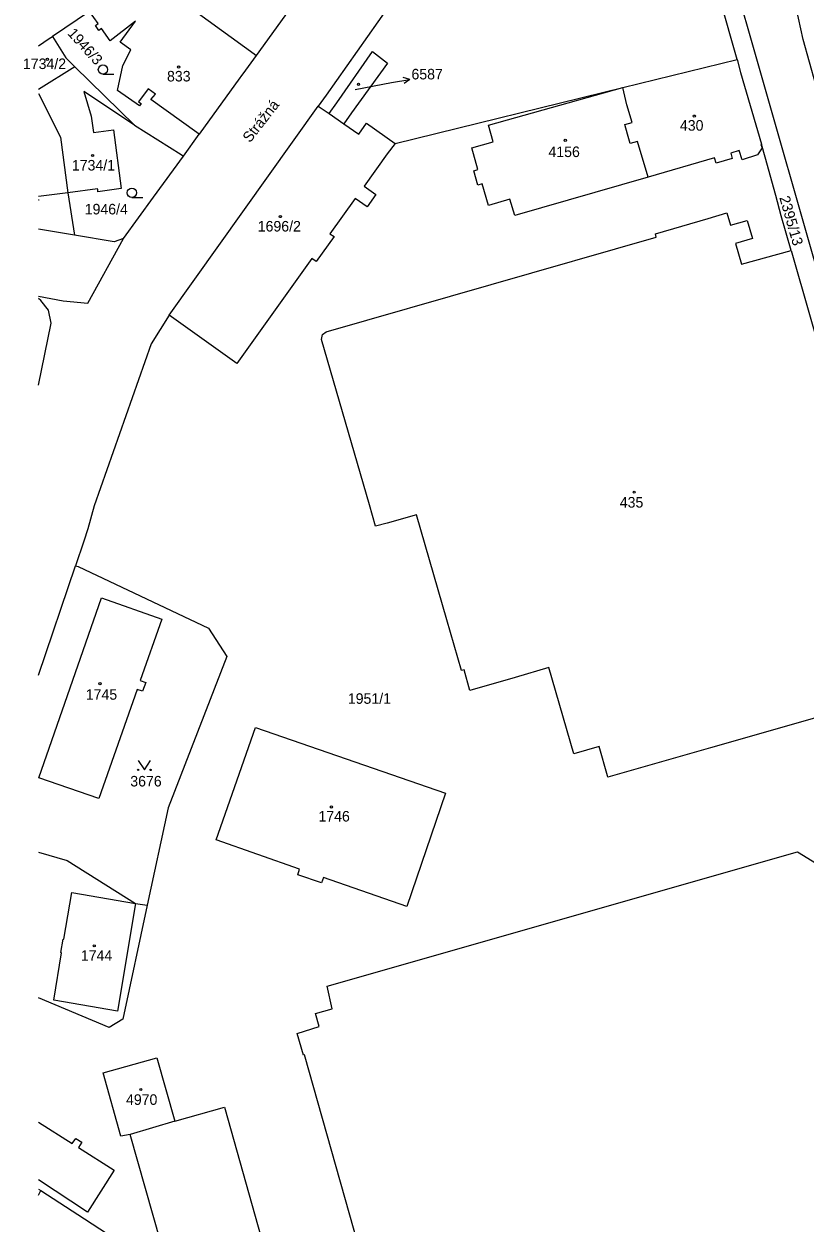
# Model space of a CAD drawing. Extents: x -667048 to -665920, y -1108425 to -1107247.
# Drawn here: x -667045.8 to -666919.9, y -1107600.6 to -1107407.4 of the extents above; entities that cross this region are included whole.
import ezdxf

# ---------------------------------------------------------------- set-up
doc = ezdxf.new("R2010")
doc.units = 0
for name, color, linetype in [('Default', 7, 'Continuous'), ('Hranice parcel', 7, 'Continuous'), ('Parcelní čísla', 7, 'Continuous'), ('Pop_ PČ_ popisy', 7, 'Continuous'), ('Značky budov', 7, 'Continuous'), ('Značky kultur', 7, 'Continuous')]:
    doc.layers.add(name, color=color, linetype=linetype)

# ---------------------------------------------------------------- blocks, each defined once
blk = doc.blocks.new('3.041')
at = {"layer": 'Default'}
blk.add_line((8, 0), (1758, 0), dxfattribs=at)
blk.add_circle((8, 750), 750, dxfattribs=at)
blk = doc.blocks.new('4.021')
at = {"layer": 'Default'}
blk.add_circle((-7, 1), 175, dxfattribs=at)
blk = doc.blocks.new('3.141')
at = {"layer": 'Default'}
blk.add_lwpolyline([(-1000, 1500), (0, 0), (1000, 1500)], dxfattribs=at)
for centre in [(-1000, 0), (1000, 0)]:
    blk.add_circle(centre, 100, dxfattribs=at)
blk = doc.blocks.new('10291')
at = {"layer": 'Default'}
for p, q in [((0, 3001), (-500, 2001)), ((0, 1), (0, 3001)), ((0, 3001), (500, 2001))]:
    blk.add_line(p, q, dxfattribs=at)

msp = doc.modelspace()

# ---------------------------------------------------------------- linework, layer by layer
at = {"layer": 'Hranice parcel'}
for points in [[(-666939.1, -1107384.26), (-666969.17, -1107379.15), (-666975.49, -1107388.12), (-666997.14, -1107418.9)], [(-666930.91, -1107413.15), (-666939.1, -1107384.26)], [(-666876.77, -1107557.56), (-666884.34, -1107546.73), (-666886.63, -1107542.65), (-666889.78, -1107536.12), (-666894, -1107526.85), (-666896.26, -1107521.29), (-666898.79, -1107514.08), (-666932.95, -1107394.82)], [(-667026.36, -1107399.54), (-667024.4, -1107400.87), (-667023.75, -1107401.31), (-667017.68, -1107405.72), (-667008.73, -1107412.23), (-667008.37, -1107412.49)], [(-666999.3, -1107399.88), (-667005.88, -1107408.97), (-667008.37, -1107412.49)], [(-666913.11, -1107435.5), (-666920.25, -1107409.89), (-666922.49, -1107399.52), (-666922.6, -1107398.73)], [(-667035.26, -1107405.41), (-667041.21, -1107409.4)], [(-667030.29, -1107410.32), (-667027.84, -1107406.98), (-667031.91, -1107410.1), (-667033.31, -1107408.14), (-667033.74, -1107408.45), (-667034.31, -1107407.66), (-667033.87, -1107407.35), (-667035.26, -1107405.41)], [(-667043.46, -1107410.91), (-667041.77, -1107409.77), (-667041.21, -1107409.4)], [(-667041.21, -1107409.4), (-667039.07, -1107412.88), (-667037.6, -1107414.3)], [(-667029.88, -1107414.11), (-667028.58, -1107411.57), (-667030.29, -1107410.32)], [(-667008.37, -1107412.49), (-667010.13, -1107414.86), (-667010.89, -1107415.89), (-667011.05, -1107416.1), (-667017.56, -1107425.16)], [(-666995.42, -1107420.09), (-666989.67, -1107411.85), (-666987.21, -1107413.74), (-666993.03, -1107421.75)], [(-666949.31, -1107417.64), (-666930.91, -1107413.15)], [(-666930.91, -1107413.15), (-666930.32, -1107415.21)], [(-667037.6, -1107414.3), (-667043.46, -1107417.98)], [(-667037.6, -1107414.3), (-667027.99, -1107423.72)], [(-667017.56, -1107425.16), (-667017.93, -1107424.9), (-667025.38, -1107419.59), (-667024.61, -1107418.72), (-667025.81, -1107417.85), (-667027.33, -1107419.95), (-667026.94, -1107420.23), (-667027.2, -1107420.6), (-667030.75, -1107418.12), (-667029.88, -1107414.11)], [(-666930.32, -1107415.21), (-666926.97, -1107426.78)], [(-667043.46, -1107418.61), (-667039.93, -1107425.62), (-667038.73, -1107434.59)], [(-667027.99, -1107423.72), (-667036.18, -1107418.29), (-667034.98, -1107422.28), (-667034.63, -1107424.91), (-667031.39, -1107424.48), (-667030.13, -1107433.94), (-667033.89, -1107434.45), (-667033.93, -1107434.14), (-667033.95, -1107433.95), (-667038.73, -1107434.59)], [(-666997.14, -1107418.9), (-666998.38, -1107420.63)], [(-666985.98, -1107426.64), (-666949.31, -1107417.64)], [(-666945.24, -1107432.09), (-666966.73, -1107438.28), (-666967.5, -1107435.63), (-666970.97, -1107436.64), (-666971.98, -1107433.18), (-666972.65, -1107433.37), (-666973.32, -1107431.07), (-666972.65, -1107430.88), (-666973.66, -1107427.39), (-666970.18, -1107426.38), (-666970.96, -1107423.72), (-666949.31, -1107417.64)], [(-666945.24, -1107432.09), (-666946.92, -1107426.33), (-666948.11, -1107426.67), (-666948.56, -1107425.14), (-666949, -1107423.6), (-666947.81, -1107423.26), (-666948.64, -1107420.43), (-666949.31, -1107417.64)], [(-667022.4, -1107454.32), (-666998.38, -1107420.63)], [(-666998.38, -1107420.63), (-666996.64, -1107421.83)], [(-666996.64, -1107421.83), (-666995.42, -1107420.09)], [(-666996.64, -1107421.83), (-666994.28, -1107423.47)], [(-666993.03, -1107421.75), (-666994.28, -1107423.47)], [(-667027.99, -1107423.72), (-667020.5, -1107428.45)], [(-667020.13, -1107428.71), (-667017.56, -1107425.16)], [(-666994.28, -1107423.47), (-666991.86, -1107425.15), (-666990.64, -1107423.41), (-666985.98, -1107426.64)], [(-666985.98, -1107426.64), (-666987.28, -1107428.33), (-666991.01, -1107433.53), (-666989.09, -1107434.86), (-666990.53, -1107436.87), (-666992.45, -1107435.54), (-666996.51, -1107441.2), (-666995.83, -1107441.67), (-666998.72, -1107445.69), (-666999.4, -1107445.22), (-667011.53, -1107462.12), (-667022.4, -1107454.32)], [(-666926.97, -1107426.78), (-666927.05, -1107426.8), (-666926.88, -1107427.38), (-666927.58, -1107428.51), (-666930.08, -1107429.3), (-666930.55, -1107427.82), (-666931.92, -1107428.22), (-666931.67, -1107429.08), (-666934.26, -1107429.84), (-666934.51, -1107428.97), (-666945.24, -1107432.09)], [(-666923.78, -1107438.31), (-666924.65, -1107435.04), (-666926.39, -1107428.87), (-666926.97, -1107426.78)], [(-667029.75, -1107441.98), (-667024.93, -1107435.33), (-667020.13, -1107428.71)], [(-667020.5, -1107428.45), (-667020.13, -1107428.71)], [(-667038.73, -1107434.59), (-667043.46, -1107435.23)], [(-667038.73, -1107434.59), (-667037.69, -1107441.43)], [(-667043.46, -1107435.67), (-667043.44, -1107435.78), (-667043.46, -1107435.78)], [(-666909.41, -1107516.68), (-666935.2, -1107524.05), (-666951.74, -1107528.77), (-666951.8, -1107528.57), (-666953.12, -1107523.85), (-666957.23, -1107525.01), (-666961.21, -1107511.12), (-666966.67, -1107512.7), (-666973.95, -1107514.81), (-666974.85, -1107511.45), (-666975.33, -1107511.59), (-666977.68, -1107503.41), (-666982.55, -1107486.49), (-666987.31, -1107487.83), (-666989.17, -1107488.35), (-666990.14, -1107484.88), (-666997.85, -1107458.23), (-666997.69, -1107457.45), (-666997.12, -1107457.02), (-666943.94, -1107441.76), (-666944.06, -1107441.22), (-666935.56, -1107438.73), (-666932.54, -1107437.85), (-666931.97, -1107439.83), (-666929.29, -1107439.06), (-666928.42, -1107441.96), (-666931.15, -1107442.76), (-666930.19, -1107446.1)], [(-666922.18, -1107443.88), (-666923.78, -1107438.31)], [(-667037.69, -1107441.43), (-667043.46, -1107440.45)], [(-667043.46, -1107451.24), (-667039.48, -1107451.99), (-667035.5, -1107452.41), (-667029.75, -1107441.98)], [(-667031.28, -1107442.52), (-667037.69, -1107441.43)], [(-667029.75, -1107441.98), (-667031.28, -1107442.52)], [(-666930.19, -1107446.1), (-666922.18, -1107443.88)], [(-666922.18, -1107443.88), (-666903.37, -1107509.56), (-666902.18, -1107513.45)], [(-667043.46, -1107465.63), (-667041.43, -1107455.64), (-667041.87, -1107453.53), (-667043.07, -1107451.95), (-667043.46, -1107451.64)], [(-667022.4, -1107454.32), (-667025.32, -1107458.97)], [(-667025.32, -1107458.97), (-667034.52, -1107485.06), (-667035.51, -1107488.76), (-667036.18, -1107490.74), (-667037.52, -1107494.7)], [(-667043.46, -1107512.33), (-667037.52, -1107494.7)], [(-667037.52, -1107494.7), (-667037.09, -1107494.85)], [(-667037.09, -1107494.85), (-667016.08, -1107504.77), (-667013.14, -1107509.35), (-667022.57, -1107533.69), (-667025.95, -1107549.42)], [(-667033.32, -1107499.86), (-667023.61, -1107503.31), (-667027.08, -1107513.2), (-667026.19, -1107513.51), (-667026.69, -1107514.93), (-667027.57, -1107514.62), (-667033.76, -1107532.2), (-667043.43, -1107528.87), (-667033.32, -1107499.86)], [(-667001.7, -1107544.48), (-667001.39, -1107543.57), (-667014.82, -1107538.89), (-667008.51, -1107520.76), (-666977.88, -1107531.36), (-666984.14, -1107549.59), (-666997.55, -1107544.92), (-666997.86, -1107545.82), (-667001.7, -1107544.48)], [(-667043.46, -1107540.87), (-667038.85, -1107542.17), (-667027.86, -1107549.12)], [(-666970.95, -1107695.22), (-666976.59, -1107675.49), (-666971.89, -1107674.42), (-666985.05, -1107628.31), (-666985.31, -1107628.39), (-666987.06, -1107622.39), (-666986.8, -1107622.31), (-667000.62, -1107573.5), (-667000.76, -1107573.54), (-667001.78, -1107570.07), (-666998.23, -1107568.96), (-666998.83, -1107566.87), (-666996.16, -1107566.11), (-666996.94, -1107562.47), (-666921.16, -1107540.78), (-666917.42, -1107543.09), (-666913.29, -1107542), (-666908.38, -1107559.19), (-666898.23, -1107556.28), (-666897.4, -1107559.14)], [(-667027.86, -1107549.12), (-667030.75, -1107566.49), (-667041.02, -1107564.7), (-667039.74, -1107557.06), (-667039.87, -1107557.04), (-667039.51, -1107554.86), (-667039.38, -1107554.88), (-667038.12, -1107547.36), (-667027.86, -1107549.12)], [(-667025.95, -1107549.42), (-667029.88, -1107567.75)], [(-667027.86, -1107549.12), (-667025.95, -1107549.42)], [(-667032.1, -1107569.09), (-667043.46, -1107564.31)], [(-667029.88, -1107567.75), (-667032.1, -1107569.09)], [(-667028.7, -1107586.32), (-667030.18, -1107586.64), (-667033.06, -1107576.41), (-667024.4, -1107573.98), (-667021.52, -1107584.2)], [(-667021.52, -1107584.2), (-667013.51, -1107581.95), (-666995.3, -1107646.66), (-667002.77, -1107648.84), (-666999.12, -1107661.88), (-666995.66, -1107661.07), (-666992.44, -1107672.12), (-666995.9, -1107673.13), (-666995.94, -1107672.98)], [(-667043.46, -1107584.35), (-667038.02, -1107587.81), (-667037.48, -1107586.97), (-667036.51, -1107587.59), (-667037.05, -1107588.43), (-667031.27, -1107592.11), (-667035.57, -1107598.86)], [(-667021.52, -1107584.2), (-667028.7, -1107586.32)], [(-666995.94, -1107672.98), (-667003.61, -1107675.01), (-667003.57, -1107675.15), (-667006.92, -1107676.1), (-667010.04, -1107665.09), (-667006.69, -1107663.93), (-667028.7, -1107586.32)], [(-667035.57, -1107598.86), (-667043.46, -1107593.65)], [(-667043.46, -1107595.14), (-667043.07, -1107595.39)], [(-667043.46, -1107596.14), (-667043.07, -1107595.39)], [(-667043.07, -1107595.39), (-667036.05, -1107599.95), (-667028.46, -1107604.89), (-667027.63, -1107605.43)]]:
    msp.add_lwpolyline(points, dxfattribs=at)
at = {"layer": 'Pop_ PČ_ popisy'}
msp.add_lwpolyline([(-666992.46, -1107417.94), (-666986.59, -1107416.86)], dxfattribs=at)

# ---------------------------------------------------------------- block references
at = {"layer": 'Pop_ PČ_ popisy', "xscale": 0.0010000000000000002, "yscale": 0.0010000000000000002, "rotation": -79.99999995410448}
msp.add_blockref('10291', (-666986.59, -1107416.86), dxfattribs=at)
at = {"layer": 'Značky budov', "xscale": 0.0010000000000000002, "yscale": 0.0010000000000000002}
for p in [(-667042.03, -1107413.1), (-667020.88, -1107414.35), (-666991.9, -1107417.13), (-666937.79, -1107422.25), (-666958.57, -1107426.15), (-667034.75, -1107428.61), (-667004.48, -1107438.44), (-666947.48, -1107482.85), (-667033.56, -1107513.69), (-666996.26, -1107533.57), (-667034.48, -1107555.95), (-667026.98, -1107579.09)]:
    msp.add_blockref('4.021', p, dxfattribs=at)
at = {"layer": 'Značky kultur', "xscale": 0.0010000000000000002, "yscale": 0.0010000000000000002}
for name, p in [('3.041', (-667033.09, -1107415.51)), ('3.041', (-667028.42, -1107435.36)), ('3.141', (-667026.41, -1107527.6))]:
    msp.add_blockref(name, p, dxfattribs=at)

# ---------------------------------------------------------------- texts
at = {"layer": 'Parcelní čísla'}
for s, rotation, p in [('1946/3', 312, (-667038.89, -1107409)), ('2395/13', 286, (-666924.11, -1107435.38))]:
    msp.add_text(s, height=1.7, rotation=rotation, dxfattribs=at).set_placement(p)
for s, p in [('1734/2', (-667045.98, -1107414.67)), ('833', (-667022.76, -1107416.67)), ('6587', (-666983.37, -1107416.34)), ('430', (-666940.11, -1107424.6)), ('4156', (-666961.29, -1107428.85)), ('1734/1', (-667038.09, -1107431.02)), ('1946/4', (-667036.02, -1107438.09)), ('1696/2', (-667008.14, -1107440.85)), ('435', (-666949.8, -1107485.33)), ('1745', (-667035.85, -1107516.29)), ('1951/1', (-666993.62, -1107516.95)), ('3676', (-667028.68, -1107530.27)), ('1746', (-666998.36, -1107535.92)), ('1744', (-667036.64, -1107558.36)), ('4970', (-667029.37, -1107581.57))]:
    msp.add_text(s, height=1.7, dxfattribs=at).set_placement(p)
at = {"layer": 'Pop_ PČ_ popisy'}
msp.add_text('Strážná', height=1.7, rotation=52, dxfattribs=at).set_placement((-667009.39, -1107426.64))

doc.saveas('drawing.dxf')
